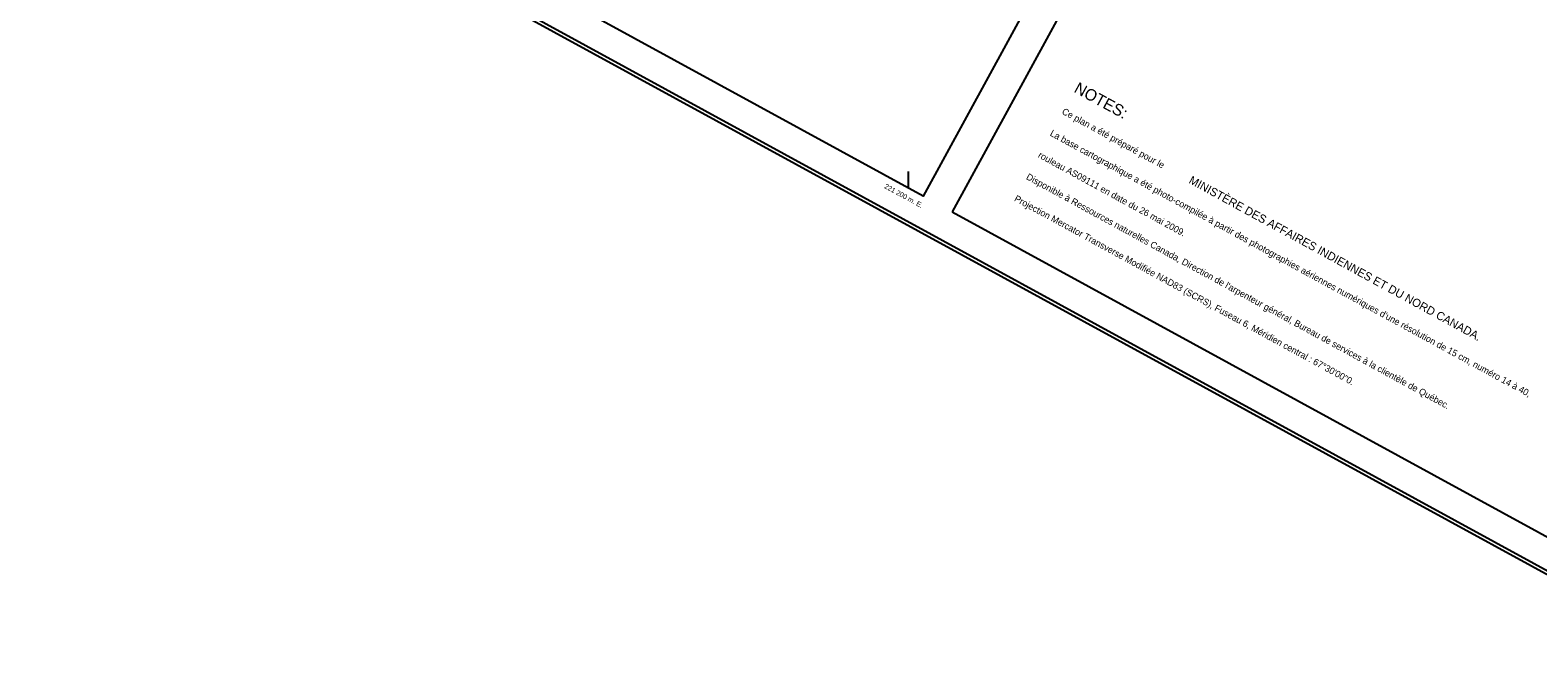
# Model space of a CAD drawing. Extents: x 219136 to 222520, y 5421589 to 5424530.
# Drawn here: x 220669 to 221580, y 5421596 to 5421973 of the extents above; entities that cross this region are included whole.
import ezdxf

# ---------------------------------------------------------------- set-up
doc = ezdxf.new("R2010")
doc.units = 0
for name, color, linetype in [('Level 60', 7, 'Continuous'), ('Level 61', 7, 'Continuous'), ('Level 62', 7, 'Continuous')]:
    doc.layers.add(name, color=color, linetype=linetype)

msp = doc.modelspace()

# ---------------------------------------------------------------- linework, layer by layer
at = {"layer": 'Level 60'}
for points in [[(219135.93, 5422982.66), (219981.09, 5424529.89), (222519.95, 5423143.06), (221674.79, 5421595.83), (219135.93, 5422982.66)], [(219138.65, 5422983.46), (219981.9, 5424527.19), (222517.24, 5423142.28), (221673.99, 5421598.55), (219138.65, 5422983.46)], [(221226.31, 5421863.6), (221663.34, 5421624.89), (222488.32, 5423135.3), (222051.3, 5423374), (221226.31, 5421863.6)]]:
    msp.add_lwpolyline(points, dxfattribs=at)
msp.add_lwpolyline([(219164.83, 5422989.67), (219989.85, 5424500.03), (222033.74, 5423383.57), (221208.72, 5421873.21)], close=True, dxfattribs=at)
at = {"layer": 'Level 61'}
msp.add_line((221200, 5421877.97), (221200, 5421887.97), dxfattribs=at)

# ---------------------------------------------------------------- texts
msp.add_text('221 200 m. E.', height=3, rotation=331.35471, dxfattribs=at).set_placement((221185.01, 5421878.18))
at = {"layer": 'Level 62'}
for s, height, p in [('NOTES:', 7, (221299.45, 5421936.27)), ('Ce plan a été préparé pour le ', 4, (221292.26, 5421923.11)), ("La base cartographique a été photo-compilée à partir des photographies aériennes numériques d'une résolution de 15 cm, numéro 14 à 40,", 4.00002, (221285.07, 5421909.94)), ('rouleau AS09111 en date du 26 mai 2009.', 4, (221277.88, 5421896.78)), ("Disponible à Ressources naturelles Canada, Direction de l'arpenteur général, Bureau de services à la clientèle de Québec.", 4.00002, (221270.69, 5421883.61)), ('MINISTÈRE DES AFFAIRES INDIENNES ET DU NORD CANADA.', 5, (221368.98, 5421881.26)), ('Projection Mercator Transverse Modifiée NAD83 (SCRS), Fuseau 6, Méridien central : 67°30\'00"0.', 4, (221263.5, 5421870.45))]:
    msp.add_text(s, height=height, rotation=331.3379, dxfattribs=at).set_placement(p)

doc.saveas('drawing.dxf')
